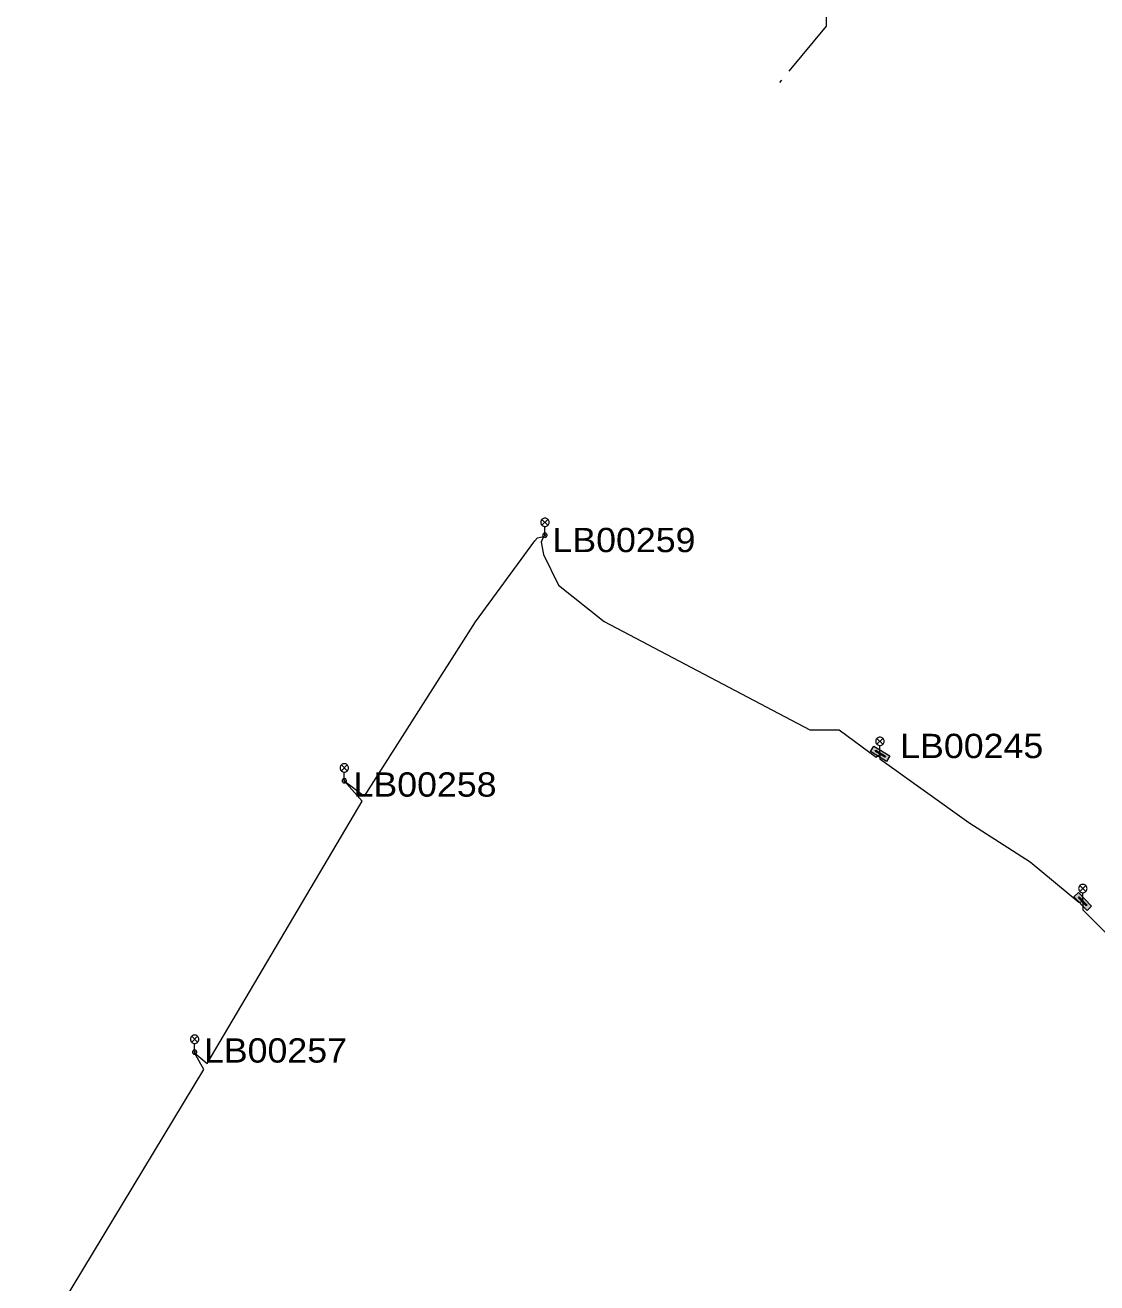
# Model space of a CAD drawing. Extents: x -688049 to -687261, y -973611 to -973038.
# Drawn here: x -687913.4 to -687817.8, y -973486.2 to -973374.1 of the extents above; entities that cross this region are included whole.
import ezdxf

# ---------------------------------------------------------------- set-up
doc = ezdxf.new("R2010")
doc.units = 0
doc.header["$LTSCALE"] = 0.87
doc.linetypes.add('LONG_DASH_SHORT_DASH', pattern=[9.9, 6, -1.2, 1.5, -1.2])
doc.layers.add('1', color=7, linetype='Continuous', lineweight=13)

msp = doc.modelspace()

# ---------------------------------------------------------------- hatches: boundary and pattern name
at = {"layer": '1'}
for points in [[(-687836.541, -973439.705), (-687837.976, -973438.818), (-687837.681, -973438.339), (-687836.245, -973439.226)], [(-687836.71, -973439.336), (-687837.571, -973438.804), (-687837.512, -973438.708), (-687836.651, -973439.24)], [(-687818.653, -973453.001), (-687819.83, -973451.792), (-687819.427, -973451.399), (-687818.25, -973452.608)], [(-687818.727, -973452.602), (-687819.434, -973451.877), (-687819.353, -973451.798), (-687818.646, -973452.523)]]:
    msp.add_hatch(color=256, dxfattribs=at).paths.add_polyline_path(points)

# ---------------------------------------------------------------- linework, layer by layer
for p, q in [((-687867.285, -973418.125), (-687866.755, -973418.655)), ((-687867.285, -973418.655), (-687866.755, -973418.125)), ((-687867.02, -973419.54), (-687867.02, -973418.765)), ((-687837.405, -973437.655), (-687836.875, -973438.185)), ((-687837.405, -973438.185), (-687836.875, -973437.655)), ((-687837.14, -973439.07), (-687837.14, -973438.295)), ((-687885.184, -973440.026), (-687884.654, -973440.556)), ((-687885.184, -973440.556), (-687884.654, -973440.026)), ((-687884.919, -973441.441), (-687884.919, -973440.666)), ((-687819.305, -973450.785), (-687818.775, -973451.315)), ((-687819.305, -973451.315), (-687818.775, -973450.785)), ((-687819.04, -973452.2), (-687819.04, -973451.425)), ((-687898.535, -973464.225), (-687898.005, -973464.755)), ((-687898.535, -973464.755), (-687898.005, -973464.225)), ((-687898.27, -973465.64), (-687898.27, -973464.865))]:
    msp.add_line(p, q, dxfattribs=at)
at = {"layer": '1', "linetype": 'LONG_DASH_SHORT_DASH'}
msp.add_lwpolyline([(-687842.38, -973365.27), (-687843.86, -973367.35), (-687841.96, -973369.05), (-687841.93, -973374.14), (-687846.1, -973379.17)], dxfattribs=at)
at = {"layer": '1'}
for points in [[(-687866.645, -973418.39), (-687866.651, -973418.325), (-687866.668, -973418.262), (-687866.695, -973418.202), (-687866.733, -973418.149), (-687866.779, -973418.103), (-687866.832, -973418.065), (-687866.892, -973418.038), (-687866.955, -973418.021), (-687867.02, -973418.015), (-687867.085, -973418.021), (-687867.148, -973418.038), (-687867.208, -973418.065), (-687867.261, -973418.103), (-687867.307, -973418.149), (-687867.345, -973418.202), (-687867.372, -973418.262), (-687867.389, -973418.325), (-687867.395, -973418.39), (-687867.389, -973418.455), (-687867.372, -973418.518), (-687867.345, -973418.578), (-687867.307, -973418.631), (-687867.261, -973418.677), (-687867.208, -973418.715), (-687867.148, -973418.742), (-687867.085, -973418.759), (-687867.02, -973418.765), (-687866.955, -973418.759), (-687866.892, -973418.742), (-687866.832, -973418.715), (-687866.779, -973418.677), (-687866.733, -973418.631), (-687866.695, -973418.578), (-687866.668, -973418.518), (-687866.651, -973418.455)], [(-687866.83, -973419.54), (-687866.833, -973419.507), (-687866.841, -973419.475), (-687866.855, -973419.445), (-687866.874, -973419.418), (-687866.898, -973419.394), (-687866.925, -973419.375), (-687866.955, -973419.361), (-687866.987, -973419.353), (-687867.02, -973419.35), (-687867.053, -973419.353), (-687867.085, -973419.361), (-687867.115, -973419.375), (-687867.142, -973419.394), (-687867.166, -973419.418), (-687867.185, -973419.445), (-687867.199, -973419.475), (-687867.207, -973419.507), (-687867.21, -973419.54), (-687867.207, -973419.573), (-687867.199, -973419.605), (-687867.185, -973419.635), (-687867.166, -973419.662), (-687867.142, -973419.686), (-687867.115, -973419.705), (-687867.085, -973419.719), (-687867.053, -973419.727), (-687867.02, -973419.73), (-687866.987, -973419.727), (-687866.955, -973419.719), (-687866.925, -973419.705), (-687866.898, -973419.686), (-687866.874, -973419.662), (-687866.855, -973419.635), (-687866.841, -973419.605), (-687866.833, -973419.573)], [(-687866.97, -973419.54), (-687866.971, -973419.531), (-687866.973, -973419.523), (-687866.977, -973419.515), (-687866.982, -973419.508), (-687866.988, -973419.502), (-687866.995, -973419.497), (-687867.003, -973419.493), (-687867.011, -973419.491), (-687867.02, -973419.49), (-687867.029, -973419.491), (-687867.037, -973419.493), (-687867.045, -973419.497), (-687867.052, -973419.502), (-687867.058, -973419.508), (-687867.063, -973419.515), (-687867.067, -973419.523), (-687867.069, -973419.531), (-687867.07, -973419.54), (-687867.069, -973419.549), (-687867.067, -973419.557), (-687867.063, -973419.565), (-687867.058, -973419.572), (-687867.052, -973419.578), (-687867.045, -973419.583), (-687867.037, -973419.587), (-687867.029, -973419.589), (-687867.02, -973419.59), (-687867.011, -973419.589), (-687867.003, -973419.587), (-687866.995, -973419.583), (-687866.988, -973419.578), (-687866.982, -973419.572), (-687866.977, -973419.565), (-687866.973, -973419.557), (-687866.971, -973419.549)], [(-687836.541, -973439.705), (-687837.976, -973438.818), (-687837.681, -973438.339), (-687836.245, -973439.226)], [(-687836.541, -973439.705), (-687837.976, -973438.818), (-687837.681, -973438.339), (-687836.245, -973439.226)], [(-687836.765, -973437.92), (-687836.771, -973437.855), (-687836.788, -973437.792), (-687836.815, -973437.732), (-687836.853, -973437.679), (-687836.899, -973437.633), (-687836.952, -973437.595), (-687837.012, -973437.568), (-687837.075, -973437.551), (-687837.14, -973437.545), (-687837.205, -973437.551), (-687837.268, -973437.568), (-687837.328, -973437.595), (-687837.381, -973437.633), (-687837.427, -973437.679), (-687837.465, -973437.732), (-687837.492, -973437.792), (-687837.509, -973437.855), (-687837.515, -973437.92), (-687837.509, -973437.985), (-687837.492, -973438.048), (-687837.465, -973438.107), (-687837.427, -973438.161), (-687837.381, -973438.207), (-687837.328, -973438.245), (-687837.268, -973438.272), (-687837.205, -973438.289), (-687837.14, -973438.295), (-687837.075, -973438.289), (-687837.012, -973438.272), (-687836.952, -973438.245), (-687836.899, -973438.207), (-687836.853, -973438.161), (-687836.815, -973438.107), (-687836.788, -973438.048), (-687836.771, -973437.985)], [(-687836.71, -973439.336), (-687837.571, -973438.804), (-687837.512, -973438.708), (-687836.651, -973439.24)], [(-687884.544, -973440.291), (-687884.55, -973440.226), (-687884.567, -973440.163), (-687884.594, -973440.104), (-687884.632, -973440.05), (-687884.678, -973440.004), (-687884.732, -973439.966), (-687884.791, -973439.939), (-687884.854, -973439.922), (-687884.919, -973439.916), (-687884.984, -973439.922), (-687885.047, -973439.939), (-687885.106, -973439.966), (-687885.16, -973440.004), (-687885.206, -973440.05), (-687885.244, -973440.104), (-687885.271, -973440.163), (-687885.288, -973440.226), (-687885.294, -973440.291), (-687885.288, -973440.356), (-687885.271, -973440.419), (-687885.244, -973440.478), (-687885.206, -973440.532), (-687885.16, -973440.578), (-687885.106, -973440.616), (-687885.047, -973440.643), (-687884.984, -973440.66), (-687884.919, -973440.666), (-687884.854, -973440.66), (-687884.791, -973440.643), (-687884.732, -973440.616), (-687884.678, -973440.578), (-687884.632, -973440.532), (-687884.594, -973440.478), (-687884.567, -973440.419), (-687884.55, -973440.356)], [(-687884.729, -973441.441), (-687884.732, -973441.408), (-687884.74, -973441.376), (-687884.754, -973441.346), (-687884.773, -973441.319), (-687884.797, -973441.295), (-687884.824, -973441.276), (-687884.854, -973441.262), (-687884.886, -973441.254), (-687884.919, -973441.251), (-687884.952, -973441.254), (-687884.984, -973441.262), (-687885.014, -973441.276), (-687885.041, -973441.295), (-687885.065, -973441.319), (-687885.084, -973441.346), (-687885.098, -973441.376), (-687885.106, -973441.408), (-687885.109, -973441.441), (-687885.106, -973441.474), (-687885.098, -973441.506), (-687885.084, -973441.536), (-687885.065, -973441.563), (-687885.041, -973441.587), (-687885.014, -973441.606), (-687884.984, -973441.62), (-687884.952, -973441.628), (-687884.919, -973441.631), (-687884.886, -973441.628), (-687884.854, -973441.62), (-687884.824, -973441.606), (-687884.797, -973441.587), (-687884.773, -973441.563), (-687884.754, -973441.536), (-687884.74, -973441.506), (-687884.732, -973441.474)], [(-687884.869, -973441.441), (-687884.87, -973441.432), (-687884.872, -973441.424), (-687884.876, -973441.416), (-687884.881, -973441.409), (-687884.887, -973441.403), (-687884.894, -973441.398), (-687884.902, -973441.394), (-687884.91, -973441.392), (-687884.919, -973441.391), (-687884.928, -973441.392), (-687884.936, -973441.394), (-687884.944, -973441.398), (-687884.951, -973441.403), (-687884.957, -973441.409), (-687884.962, -973441.416), (-687884.966, -973441.424), (-687884.968, -973441.432), (-687884.969, -973441.441), (-687884.968, -973441.45), (-687884.966, -973441.458), (-687884.962, -973441.466), (-687884.957, -973441.473), (-687884.951, -973441.479), (-687884.944, -973441.484), (-687884.936, -973441.488), (-687884.928, -973441.49), (-687884.919, -973441.491), (-687884.91, -973441.49), (-687884.902, -973441.488), (-687884.894, -973441.484), (-687884.887, -973441.479), (-687884.881, -973441.473), (-687884.876, -973441.466), (-687884.872, -973441.458), (-687884.87, -973441.45)], [(-687818.665, -973451.05), (-687818.671, -973450.985), (-687818.688, -973450.922), (-687818.715, -973450.862), (-687818.753, -973450.809), (-687818.799, -973450.763), (-687818.852, -973450.725), (-687818.912, -973450.698), (-687818.975, -973450.681), (-687819.04, -973450.675), (-687819.105, -973450.681), (-687819.168, -973450.698), (-687819.228, -973450.725), (-687819.281, -973450.763), (-687819.327, -973450.809), (-687819.365, -973450.862), (-687819.392, -973450.922), (-687819.409, -973450.985), (-687819.415, -973451.05), (-687819.409, -973451.115), (-687819.392, -973451.178), (-687819.365, -973451.237), (-687819.327, -973451.291), (-687819.281, -973451.337), (-687819.228, -973451.375), (-687819.168, -973451.402), (-687819.105, -973451.419), (-687819.04, -973451.425), (-687818.975, -973451.419), (-687818.912, -973451.402), (-687818.852, -973451.375), (-687818.799, -973451.337), (-687818.753, -973451.291), (-687818.715, -973451.237), (-687818.688, -973451.178), (-687818.671, -973451.115)], [(-687818.653, -973453.001), (-687819.83, -973451.792), (-687819.427, -973451.399), (-687818.25, -973452.608)], [(-687818.653, -973453.001), (-687819.83, -973451.792), (-687819.427, -973451.399), (-687818.25, -973452.608)], [(-687818.727, -973452.602), (-687819.434, -973451.877), (-687819.353, -973451.798), (-687818.646, -973452.523)], [(-687897.895, -973464.49), (-687897.901, -973464.425), (-687897.918, -973464.362), (-687897.945, -973464.302), (-687897.983, -973464.249), (-687898.029, -973464.203), (-687898.082, -973464.165), (-687898.142, -973464.138), (-687898.205, -973464.121), (-687898.27, -973464.115), (-687898.335, -973464.121), (-687898.398, -973464.138), (-687898.458, -973464.165), (-687898.511, -973464.203), (-687898.557, -973464.249), (-687898.595, -973464.302), (-687898.622, -973464.362), (-687898.639, -973464.425), (-687898.645, -973464.49), (-687898.639, -973464.555), (-687898.622, -973464.618), (-687898.595, -973464.678), (-687898.557, -973464.731), (-687898.511, -973464.777), (-687898.458, -973464.815), (-687898.398, -973464.842), (-687898.335, -973464.859), (-687898.27, -973464.865), (-687898.205, -973464.859), (-687898.142, -973464.842), (-687898.082, -973464.815), (-687898.029, -973464.777), (-687897.983, -973464.731), (-687897.945, -973464.678), (-687897.918, -973464.618), (-687897.901, -973464.555)], [(-687898.08, -973465.64), (-687898.083, -973465.607), (-687898.091, -973465.575), (-687898.105, -973465.545), (-687898.124, -973465.518), (-687898.148, -973465.494), (-687898.175, -973465.475), (-687898.205, -973465.461), (-687898.237, -973465.453), (-687898.27, -973465.45), (-687898.303, -973465.453), (-687898.335, -973465.461), (-687898.365, -973465.475), (-687898.392, -973465.494), (-687898.416, -973465.518), (-687898.435, -973465.545), (-687898.449, -973465.575), (-687898.457, -973465.607), (-687898.46, -973465.64), (-687898.457, -973465.673), (-687898.449, -973465.705), (-687898.435, -973465.735), (-687898.416, -973465.762), (-687898.392, -973465.786), (-687898.365, -973465.805), (-687898.335, -973465.819), (-687898.303, -973465.827), (-687898.27, -973465.83), (-687898.237, -973465.827), (-687898.205, -973465.819), (-687898.175, -973465.805), (-687898.148, -973465.786), (-687898.124, -973465.762), (-687898.105, -973465.735), (-687898.091, -973465.705), (-687898.083, -973465.673)], [(-687898.22, -973465.64), (-687898.221, -973465.631), (-687898.223, -973465.623), (-687898.227, -973465.615), (-687898.232, -973465.608), (-687898.238, -973465.602), (-687898.245, -973465.597), (-687898.253, -973465.593), (-687898.261, -973465.591), (-687898.27, -973465.59), (-687898.279, -973465.591), (-687898.287, -973465.593), (-687898.295, -973465.597), (-687898.302, -973465.602), (-687898.308, -973465.608), (-687898.313, -973465.615), (-687898.317, -973465.623), (-687898.319, -973465.631), (-687898.32, -973465.64), (-687898.319, -973465.649), (-687898.317, -973465.657), (-687898.313, -973465.665), (-687898.308, -973465.672), (-687898.302, -973465.678), (-687898.295, -973465.683), (-687898.287, -973465.687), (-687898.279, -973465.689), (-687898.27, -973465.69), (-687898.261, -973465.689), (-687898.253, -973465.687), (-687898.245, -973465.683), (-687898.238, -973465.678), (-687898.232, -973465.672), (-687898.227, -973465.665), (-687898.223, -973465.657), (-687898.221, -973465.649)]]:
    msp.add_lwpolyline(points, close=True, dxfattribs=at)
for points in [[(-687884.919, -973441.441), (-687883.108, -973442.82), (-687873.209, -973427.277), (-687867.937, -973420.036), (-687867.674, -973419.772), (-687867.153, -973419.662)], [(-687867.153, -973419.662), (-687867.351, -973420.154), (-687867.14, -973421.268), (-687865.823, -973424.001), (-687861.734, -973427.238), (-687843.382, -973436.903), (-687840.761, -973436.903), (-687837.464, -973439.323), (-687837.14, -973439.07)], [(-687837.14, -973439.07), (-687837.14, -973439.481), (-687829.222, -973445.161), (-687823.74, -973448.682), (-687819.406, -973452.278), (-687819.04, -973452.2)], [(-687898.272, -973465.715), (-687897.153, -973466.649), (-687883.336, -973443.244), (-687884.919, -973441.441)], [(-687819.04, -973452.2), (-687819.04, -973452.574), (-687819.04, -973452.949), (-687813.849, -973458.152), (-687811.678, -973460.195), (-687802.859, -973467.045), (-687801.322, -973468.176), (-687799.08, -973470.678), (-687800.562, -973472.364), (-687800.195, -973472.675)], [(-687913.39, -973492.15), (-687912.727, -973492.501), (-687897.443, -973467.178), (-687898.272, -973465.715)]]:
    msp.add_lwpolyline(points, dxfattribs=at)

# ---------------------------------------------------------------- texts
at = {"layer": '1', "width": 1.1}
for s, p in [('LB00259', (-687866.353, -973421.05)), ('LB00245', (-687835.332, -973439.415)), ('LB00258', (-687884.099, -973442.855)), ('LB00257', (-687897.443, -973466.572))]:
    msp.add_text(s, height=2.167, dxfattribs=at).set_placement(p)

doc.saveas('drawing.dxf')
